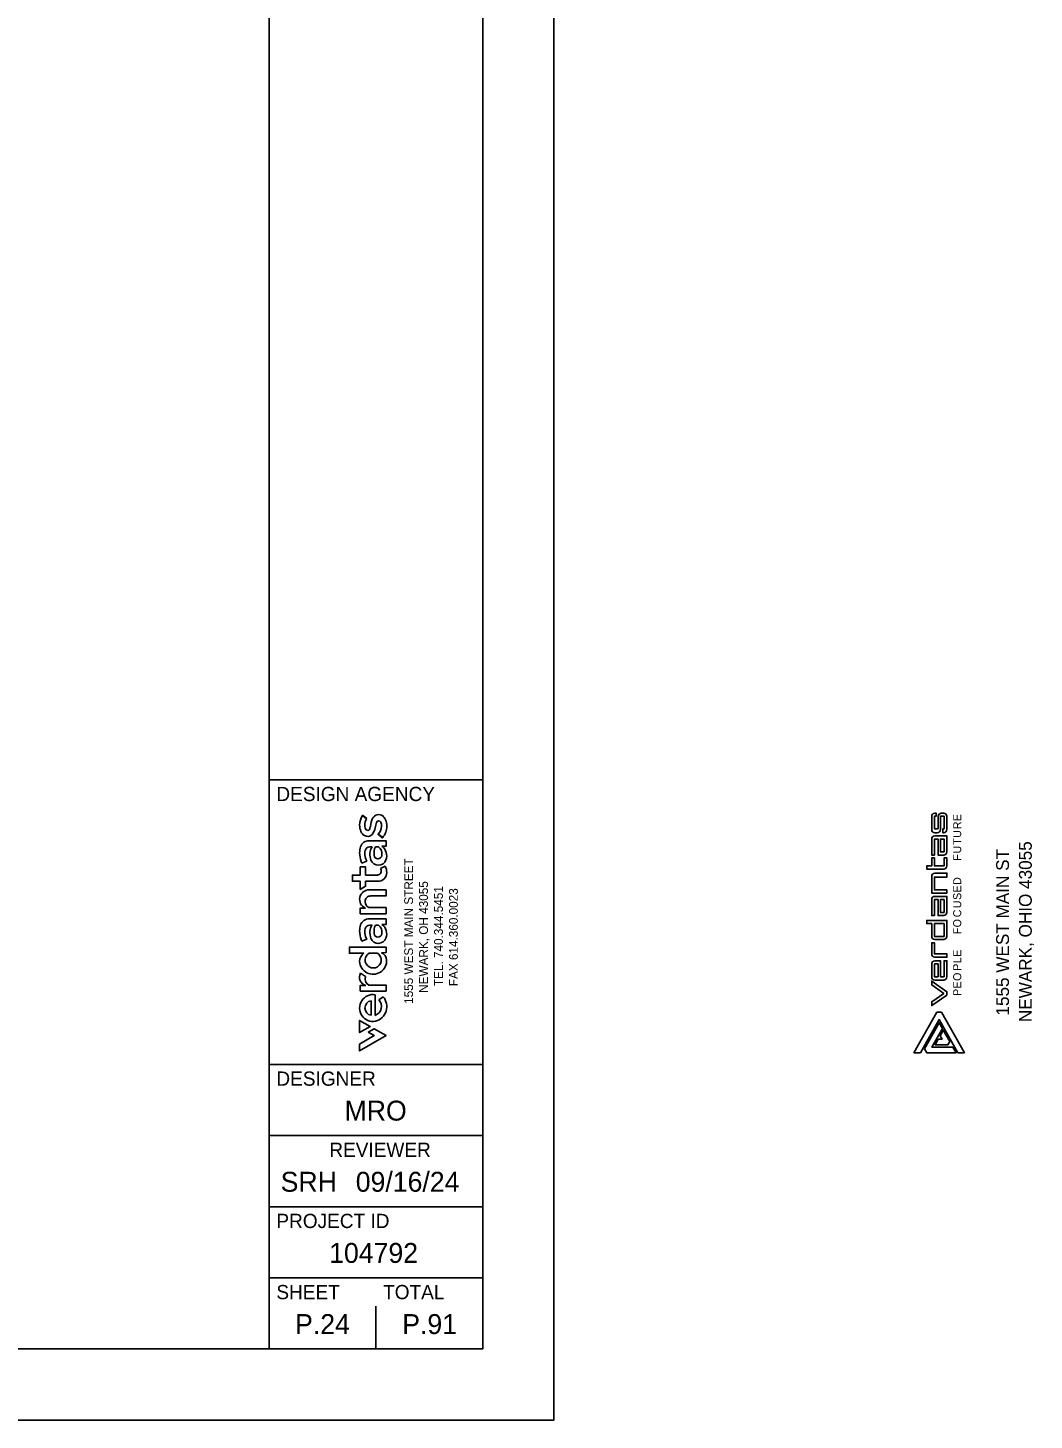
# Model space of a CAD drawing. Extents: x 0 to 37.4, y 0 to 22.
# Drawn here: x 30.3 to 37.37, y 0 to 9.78 of the extents above; entities that cross this region are included whole.
import ezdxf

# ---------------------------------------------------------------- set-up
doc = ezdxf.new("R2010")
doc.units = 0
for name, color, linetype in [('CS-ANNO-TTLB-LOGO', 7, 'Continuous'), ('Default', 7, 'Continuous'), ('SH_Border', 7, 'Continuous'), ('SH_Cut_Line', 7, 'Continuous'), ('SH_Data', 7, 'Continuous'), ('SH_Text', 7, 'Continuous')]:
    doc.layers.add(name, color=color, linetype=linetype)

msp = doc.modelspace()

# ---------------------------------------------------------------- linework, layer by layer
at = {"layer": 'CS-ANNO-TTLB-LOGO'}
for p, q in [((36.6549, 4.2432), (36.6549, 4.1504)), ((36.6858, 4.2657), (36.6774, 4.2657)), ((36.7392, 4.2657), (36.7224, 4.2657)), ((36.7617, 4.1504), (36.7617, 4.2432)), ((36.6774, 4.1279), (36.6942, 4.1279)), ((36.6549, 3.9704), (36.6549, 4.0829)), ((36.6549, 3.5456), (36.6549, 3.6581)), ((36.6774, 3.3769), (36.7392, 3.3769)), ((36.6549, 3.2053), (36.6549, 3.1153)), ((36.7617, 3.1153), (36.7617, 3.2278)), ((36.6774, 3.0928), (36.7392, 3.0928))]:
    msp.add_line(p, q, dxfattribs=at)
for points in [[(36.6999, 4.2432), (36.6999, 4.156), (36.6745, 4.156), (36.6745, 4.2432), (36.6858, 4.2432), (36.6858, 4.2657)], [(36.7167, 4.1504), (36.7167, 4.2432), (36.742, 4.2432), (36.742, 4.156), (36.7336, 4.156), (36.7336, 4.1279), (36.7392, 4.1279)], [(36.7392, 3.9704), (36.6999, 3.9704), (36.6999, 4.0829), (36.6745, 4.0829), (36.6745, 3.9704), (36.6549, 3.9704)], [(36.6774, 4.1054), (36.7617, 4.1054), (36.7617, 3.9929)], [(36.6202, 3.8944), (36.6549, 3.8944), (36.6549, 3.9506), (36.6745, 3.9506), (36.6745, 3.8944), (36.742, 3.8944), (36.742, 3.9506), (36.7617, 3.9506), (36.7617, 3.8944)], [(36.7392, 3.8719), (36.6202, 3.8719), (36.6202, 3.8944)], [(36.6549, 3.8213), (36.6549, 3.7031), (36.7617, 3.7031), (36.7617, 3.7256), (36.6745, 3.7256), (36.6745, 3.8156), (36.7617, 3.8156)], [(36.7617, 3.8156), (36.7617, 3.8438), (36.6774, 3.8438)], [(36.7392, 3.5456), (36.6999, 3.5456), (36.6999, 3.6581), (36.6745, 3.6581), (36.6745, 3.5456), (36.6549, 3.5456)], [(36.6774, 3.6806), (36.7617, 3.6806), (36.7617, 3.5681)], [(36.6202, 3.5119), (36.6202, 3.4894), (36.6549, 3.4894), (36.6549, 3.3994)], [(36.7617, 3.3994), (36.7617, 3.5119), (36.6202, 3.5119)], [(36.7617, 3.2756), (36.6745, 3.2756), (36.6745, 3.3544), (36.6549, 3.3544), (36.6549, 3.2756)], [(36.6774, 3.2531), (36.7617, 3.2531), (36.7617, 3.2756)], [(36.7617, 3.2278), (36.742, 3.2278), (36.742, 3.1153), (36.7167, 3.1153), (36.7167, 3.2278), (36.6774, 3.2278)]]:
    msp.add_lwpolyline(points, dxfattribs=at)
for points in [[(36.7167, 4.0829), (36.742, 4.0829), (36.742, 3.9929), (36.7167, 3.9929)], [(36.7167, 3.6581), (36.742, 3.6581), (36.742, 3.5681), (36.7167, 3.5681)], [(36.6745, 3.4894), (36.6745, 3.3994), (36.742, 3.3994), (36.742, 3.4894)], [(36.6999, 3.2053), (36.6745, 3.2053), (36.6745, 3.1153), (36.6999, 3.1153)], [(36.7393, 2.9991), (36.6549, 2.9399), (36.6549, 2.9125), (36.7617, 2.9873), (36.7622, 3.0105), (36.6553, 3.0853), (36.6549, 3.0582)]]:
    msp.add_lwpolyline(points, close=True, dxfattribs=at)
for centre, start, end in [((36.6774, 4.2432), 90, 180), ((36.7224, 4.2432), 90, 180), ((36.7392, 4.2432), 360, 90), ((36.6774, 4.1504), 180, 270), ((36.6942, 4.1504), 270, 0), ((36.7392, 4.1504), 270, 0), ((36.6774, 4.0829), 90, 180), ((36.7392, 3.9929), 270, 360), ((36.6774, 3.8213), 90, 180), ((36.7392, 3.8944), 270, 360), ((36.6774, 3.6581), 90, 180), ((36.7392, 3.5681), 270, 360), ((36.6774, 3.3994), 180, 270), ((36.7392, 3.3994), 270, 0), ((36.6774, 3.2756), 180, 270), ((36.6774, 3.2053), 90, 180), ((36.6774, 3.1153), 180, 270), ((36.7392, 3.1153), 270, 0)]:
    msp.add_arc(centre, 0.0225, start, end, dxfattribs=at)
at = {"layer": 'Default'}
for p, q in [((36.6549, 4.2432), (36.6549, 4.1504)), ((36.7392, 4.2657), (36.7224, 4.2657)), ((36.7617, 4.1504), (36.7617, 4.2432)), ((36.6774, 4.1279), (36.6942, 4.1279)), ((36.6774, 3.3769), (36.7392, 3.3769)), ((36.6549, 3.2053), (36.6549, 3.1153)), ((36.6774, 3.0928), (36.7392, 3.0928)), ((36.6043, 2.6089), (36.7077, 2.7921)), ((36.7303, 2.752), (36.6561, 2.6206)), ((36.7077, 2.7921), (36.7303, 2.752)), ((36.62, 2.5812), (36.6043, 2.6089)), ((36.8266, 2.5812), (36.62, 2.5812)), ((36.6561, 2.6206), (36.8044, 2.6206)), ((36.8044, 2.6206), (36.8266, 2.5812))]:
    msp.add_line(p, q, dxfattribs=at)
for points in [[(36.6999, 4.2432), (36.6999, 4.156), (36.6745, 4.156), (36.6745, 4.2432), (36.6858, 4.2432), (36.6858, 4.2657), (36.6774, 4.2657)], [(36.7167, 4.1504), (36.7167, 4.2432), (36.742, 4.2432), (36.742, 4.156), (36.7336, 4.156), (36.7336, 4.1279), (36.7392, 4.1279)], [(36.6549, 4.0829), (36.6549, 3.9704), (36.6745, 3.9704), (36.6745, 4.0829), (36.6999, 4.0829), (36.6999, 3.9704), (36.7392, 3.9704)], [(36.7617, 3.9929), (36.7617, 4.1054), (36.6774, 4.1054)], [(36.7617, 3.8944), (36.7617, 3.9506), (36.742, 3.9506), (36.742, 3.8944), (36.6745, 3.8944), (36.6745, 3.9506), (36.6549, 3.9506), (36.6549, 3.8944), (36.6202, 3.8944), (36.6202, 3.8719), (36.7392, 3.8719)], [(36.6549, 3.8213), (36.6549, 3.7031), (36.7617, 3.7031), (36.7617, 3.7256), (36.6745, 3.7256), (36.6745, 3.8156), (36.7617, 3.8156), (36.7617, 3.8438), (36.6774, 3.8438)], [(36.6549, 3.6581), (36.6549, 3.5456), (36.6745, 3.5456), (36.6745, 3.6581), (36.6999, 3.6581), (36.6999, 3.5456), (36.7392, 3.5456)], [(36.7617, 3.5681), (36.7617, 3.6806), (36.6774, 3.6806)], [(36.7617, 3.3994), (36.7617, 3.5119), (36.6202, 3.5119), (36.6202, 3.4894), (36.6549, 3.4894), (36.6549, 3.3994)], [(36.6774, 3.2531), (36.7617, 3.2531), (36.7617, 3.2756), (36.6745, 3.2756), (36.6745, 3.3544), (36.6549, 3.3544), (36.6549, 3.2756)], [(36.7617, 3.1153), (36.7617, 3.2278), (36.742, 3.2278), (36.742, 3.1153), (36.7167, 3.1153), (36.7167, 3.2278), (36.6774, 3.2278)]]:
    msp.add_lwpolyline(points, dxfattribs=at)
for points in [[(36.742, 4.0829), (36.742, 3.9929), (36.7167, 3.9929), (36.7167, 4.0829)], [(36.742, 3.6581), (36.742, 3.5681), (36.7167, 3.5681), (36.7167, 3.6581)], [(36.6745, 3.4894), (36.742, 3.4894), (36.742, 3.3994), (36.6745, 3.3994)], [(36.6999, 3.2053), (36.6999, 3.1153), (36.6745, 3.1153), (36.6745, 3.2053)], [(36.6549, 2.9399), (36.6549, 2.9125), (36.7617, 2.9873), (36.7622, 3.0105), (36.6553, 3.0853), (36.6549, 3.0582), (36.7393, 2.9991)], [(36.7077, 2.815), (36.8396, 2.5812), (36.8848, 2.5812), (36.7238, 2.8665), (36.6915, 2.8665), (36.5306, 2.5812), (36.5758, 2.5812)], [(36.5758, 2.5812), (36.7077, 2.815), (36.8396, 2.5812), (36.8848, 2.5812), (36.7238, 2.8665), (36.6915, 2.8665), (36.5306, 2.5812)], [(36.6043, 2.6089), (36.62, 2.5812), (36.8266, 2.5812), (36.8044, 2.6206), (36.6561, 2.6206), (36.7303, 2.752), (36.7077, 2.7921)], [(36.7008, 2.6768), (36.6786, 2.6374), (36.769, 2.6374), (36.7819, 2.6604), (36.7367, 2.7406), (36.7141, 2.7005), (36.7275, 2.6768)], [(36.7008, 2.6768), (36.7275, 2.6768), (36.7141, 2.7005), (36.7367, 2.7406), (36.7819, 2.6604), (36.769, 2.6374), (36.6786, 2.6374)]]:
    msp.add_lwpolyline(points, close=True, dxfattribs=at)
for centre, start, end in [((36.6774, 4.2432), 90, 180), ((36.7224, 4.2432), 90, 180), ((36.7392, 4.2432), 360, 90), ((36.6774, 4.1504), 180, 270), ((36.6942, 4.1504), 270, 0), ((36.7392, 4.1504), 270, 0), ((36.6774, 4.0829), 90, 180), ((36.7392, 3.9929), 270, 0), ((36.6774, 3.8213), 90, 180), ((36.7392, 3.8944), 270, 0), ((36.6774, 3.6581), 90, 180), ((36.7392, 3.5681), 270, 0), ((36.6774, 3.3994), 180, 270), ((36.7392, 3.3994), 270, 0), ((36.6774, 3.2756), 180, 270), ((36.6774, 3.2053), 90, 180), ((36.6774, 3.1153), 180, 270), ((36.7392, 3.1153), 270, 0)]:
    msp.add_arc(centre, 0.0225, start, end, dxfattribs=at)
at = {"layer": 'SH_Border'}
for p, q in [((32, 0.5), (32, 21.5)), ((32, 4.5), (33.5, 4.5)), ((32, 2.5), (33.5, 2.5)), ((32, 2), (33.5, 2)), ((32, 1.5), (33.5, 1.5)), ((32, 1), (33.5, 1))]:
    msp.add_line(p, q, dxfattribs=at)
msp.add_lwpolyline([(1.5, 21.5), (33.5, 21.5), (33.5, 0.5), (1.5, 0.5)], close=True, dxfattribs=at)
at = {"layer": 'SH_Cut_Line'}
msp.add_lwpolyline([(0, 0), (34, 0), (34, 22), (0, 22)], close=True, dxfattribs=at)
at = {"layer": 'SH_Data'}
for p, q in [((32.75, 3.5), (32.75, 3.5)), ((32.75, 0.5), (32.75, 0.8)), ((32.375, 0.675), (32.375, 0.675))]:
    msp.add_line(p, q, dxfattribs=at)
at = {"layer": 'SH_Text'}
for p, q in [((32.6845, 4.2263), (32.655, 4.2488)), ((32.7172, 4.2018), (32.7108, 4.1722)), ((32.745, 4.1621), (32.749, 4.181)), ((32.7664, 4.1165), (32.7975, 4.0939)), ((32.7069, 4.0286), (32.7221, 4.0286)), ((32.7463, 4.0286), (32.7683, 4.0286)), ((32.6463, 3.9261), (32.6509, 3.9147)), ((32.8149, 3.8922), (32.7815, 3.8767)), ((32.7069, 3.4791), (32.7221, 3.4791)), ((32.7463, 3.4791), (32.7683, 3.4791)), ((32.6463, 3.3765), (32.6509, 3.3651)), ((32.7017, 3.2812), (32.759, 3.2812)), ((32.6758, 3.1185), (32.6407, 3.1397)), ((32.7158, 2.947), (32.7158, 2.8451)), ((32.7445, 2.8443), (32.7445, 2.9896)), ((32.801, 2.9757), (32.7703, 2.9546))]:
    msp.add_line(p, q, dxfattribs=at)
for points in [[(32.6861, 4.2287), (32.6559, 4.25), (32.655, 4.2488)], [(32.6845, 4.2263), (32.6861, 4.2287)], [(32.7172, 4.2018), (32.7108, 4.1722)], [(32.745, 4.1621), (32.749, 4.181)], [(32.7664, 4.1165), (32.7642, 4.1142), (32.7942, 4.0904), (32.7975, 4.0939)], [(32.7922, 4.0323), (32.8208, 4.0323), (32.8208, 4.0718), (32.702, 4.0718)], [(32.7922, 4.0323), (32.8208, 4.0323), (32.8208, 4.0718), (32.702, 4.0718)], [(32.7069, 4.0286), (32.7221, 4.0286)], [(32.7683, 4.0286), (32.7463, 4.0286)], [(32.6463, 3.9261), (32.6509, 3.9147)], [(32.6509, 3.9147), (32.6847, 3.9285), (32.6812, 3.9374)], [(32.6509, 3.9147), (32.6847, 3.9285), (32.6812, 3.9374)], [(32.7546, 3.8297), (32.6769, 3.8297), (32.6769, 3.8877), (32.6399, 3.8877), (32.6399, 3.8297), (32.5844, 3.8297), (32.5844, 3.7865), (32.6399, 3.7865), (32.6399, 3.7299), (32.6769, 3.7521), (32.6769, 3.7865), (32.7622, 3.7865)], [(32.7546, 3.8297), (32.6769, 3.8297), (32.6769, 3.8877), (32.6399, 3.8877), (32.6399, 3.8297), (32.5844, 3.8297), (32.5844, 3.7865), (32.6399, 3.7865), (32.6399, 3.7299), (32.6769, 3.7521), (32.6769, 3.7865), (32.7622, 3.7865)], [(32.8149, 3.8922), (32.7815, 3.8767)], [(32.7147, 3.6831), (32.8208, 3.6831), (32.8208, 3.7263), (32.7027, 3.7263)], [(32.7147, 3.6831), (32.8208, 3.6831), (32.8208, 3.7263), (32.7027, 3.7263)], [(32.6753, 3.5982), (32.6399, 3.5982), (32.6399, 3.5582), (32.8208, 3.5582), (32.8208, 3.6014), (32.6998, 3.6014)], [(32.6753, 3.5982), (32.6399, 3.5982), (32.6399, 3.5582), (32.8208, 3.5582), (32.8208, 3.6014), (32.6998, 3.6014)], [(32.7922, 3.4827), (32.8208, 3.4827), (32.8208, 3.5223), (32.702, 3.5223)], [(32.7922, 3.4827), (32.8208, 3.4827), (32.8208, 3.5223), (32.702, 3.5223)], [(32.7069, 3.4791), (32.7221, 3.4791)], [(32.7683, 3.4791), (32.7463, 3.4791)], [(32.6463, 3.3765), (32.6509, 3.3651)], [(32.6509, 3.3651), (32.6847, 3.3789), (32.6812, 3.3878)], [(32.6509, 3.3651), (32.6847, 3.3789), (32.6812, 3.3878)], [(32.6648, 3.2812), (32.5631, 3.2812), (32.5631, 3.3244), (32.8208, 3.3244), (32.8208, 3.2849), (32.789, 3.2848)], [(32.789, 3.2848), (32.8208, 3.2849), (32.8208, 3.3244), (32.5631, 3.3244), (32.5631, 3.2812), (32.6648, 3.2812)], [(32.7017, 3.2812), (32.759, 3.2812)], [(32.6758, 3.1185), (32.6407, 3.1397)], [(32.6786, 3.0546), (32.6398, 3.0546), (32.6398, 3.0152), (32.8207, 3.0152), (32.8207, 3.0569), (32.7008, 3.0569)], [(32.6786, 3.0546), (32.6398, 3.0546), (32.6398, 3.0152), (32.8207, 3.0152), (32.8207, 3.0569), (32.7008, 3.0569)], [(32.7158, 2.8451), (32.7158, 2.947)], [(32.7445, 2.8443), (32.7445, 2.9896)], [(32.801, 2.9757), (32.7703, 2.9546)], [(32.6351, 2.8093), (32.6351, 2.723), (32.7098, 2.7661), (32.6351, 2.8093)], [(32.6958, 2.7267), (32.7381, 2.7022), (32.6351, 2.6427), (32.6351, 2.5951), (32.8205, 2.7022), (32.737, 2.7504), (32.6958, 2.7267)]]:
    msp.add_lwpolyline(points, dxfattribs=at)
for points in [[(32.7098, 2.7661), (32.6351, 2.723), (32.6351, 2.8093)], [(32.6958, 2.7267), (32.7381, 2.7022), (32.6351, 2.6427), (32.6351, 2.5951), (32.8205, 2.7022), (32.737, 2.7504)]]:
    msp.add_lwpolyline(points, close=True, dxfattribs=at)
for centre, radius, start, end in [((32.7599, 4.1812), 0.1247, 147.22328, 179.84204), ((32.7599, 4.1812), 0.1247, 147.22328, 179.84204), ((32.761, 4.1787), 0.0901, 148.12326, 178.11353), ((32.761, 4.1787), 0.0901, 148.12326, 178.11353), ((32.8373, 4.1746), 0.1232, 154.04469, 167.21491), ((32.8373, 4.1746), 0.1232, 154.04469, 167.21491), ((32.7687, 4.2081), 0.0468, 52.70919, 154.21664), ((32.7687, 4.2081), 0.0468, 52.70919, 154.21664), ((32.7694, 4.1954), 0.0157, 26.91646, 163.60196), ((32.7694, 4.1954), 0.0157, 26.91646, 163.60196), ((32.7543, 4.1931), 0.0675, 22.82777, 50.71565), ((32.7543, 4.1931), 0.0675, 22.82777, 50.71565), ((32.7119, 4.175), 0.1136, 359.0192, 22.9257), ((32.7119, 4.175), 0.1136, 359.0192, 22.9257), ((32.7433, 4.1797), 0.1082, 179.01095, 203.55998), ((32.7433, 4.1797), 0.1082, 179.01095, 203.55998), ((32.7026, 4.1617), 0.0637, 203.36923, 237.807), ((32.7026, 4.1617), 0.0637, 203.36923, 237.807), ((32.6911, 4.1451), 0.0435, 238.94525, 317.68291), ((32.6911, 4.1451), 0.0435, 238.94525, 317.68291), ((32.7377, 4.1806), 0.0667, 179.05393, 195.69208), ((32.7377, 4.1806), 0.0667, 179.05393, 195.69208), ((32.7044, 4.1702), 0.0318, 193.85614, 223.71908), ((32.7044, 4.1702), 0.0318, 193.85614, 223.71908), ((32.6914, 4.1581), 0.0141, 224.78223, 330.43657), ((32.6914, 4.1581), 0.0141, 224.78223, 330.43657), ((32.6343, 4.1866), 0.0778, 332.90022, 349.38313), ((32.6343, 4.1866), 0.0778, 332.90022, 349.38313), ((32.6466, 4.1799), 0.1, 320.12588, 349.70225), ((32.6466, 4.1799), 0.1, 320.12588, 349.70225), ((32.838, 4.1664), 0.0902, 158.18628, 170.63281), ((32.838, 4.1664), 0.0902, 158.18628, 170.63281), ((32.7013, 4.1765), 0.0885, 317.36304, 356.92436), ((32.7013, 4.1765), 0.0885, 317.36304, 356.92436), ((32.7276, 4.175), 0.0622, 357.00773, 26.31116), ((32.7276, 4.175), 0.0622, 357.00773, 26.31116), ((32.7025, 4.1721), 0.123, 320.51657, 0.43409), ((32.7025, 4.1721), 0.123, 320.51657, 0.43409), ((32.757, 3.989), 0.1218, 160.81276, 180.93166), ((32.757, 3.989), 0.1218, 160.81276, 180.93166), ((32.7, 4.0111), 0.0607, 88.07599, 162.86424), ((32.7, 4.0111), 0.0607, 88.07599, 162.86424), ((32.7087, 3.9932), 0.0355, 92.96709, 165.223), ((32.7087, 3.9932), 0.0355, 92.96709, 165.223), ((32.8099, 3.9746), 0.1031, 148.34975, 202.47075), ((32.8099, 3.9746), 0.1031, 148.34975, 202.47075), ((32.8357, 3.9847), 0.0996, 153.83718, 188.87457), ((32.8357, 3.9847), 0.0996, 153.83718, 188.87457), ((32.7313, 3.9807), 0.0605, 348.12474, 52.36783), ((32.7313, 3.9807), 0.0605, 348.12474, 52.36783), ((32.7441, 3.9666), 0.0814, 338.27739, 53.79489), ((32.7441, 3.9666), 0.0814, 338.27739, 53.79489), ((32.8238, 3.9901), 0.1886, 180.9467, 199.83537), ((32.8238, 3.9901), 0.1886, 180.9467, 199.83537), ((32.7333, 3.9845), 0.0615, 163.25224, 179.99706), ((32.7333, 3.9845), 0.0615, 163.25224, 179.99706), ((32.8157, 3.9887), 0.144, 181.66161, 200.87137), ((32.8157, 3.9887), 0.144, 181.66161, 200.87137), ((32.7669, 3.956), 0.0563, 201.67635, 339.72677), ((32.7669, 3.956), 0.0563, 201.67635, 339.72677), ((32.7639, 3.9704), 0.0267, 182.32704, 355.37776), ((32.7639, 3.9704), 0.0267, 182.32704, 355.37776), ((32.7572, 3.8595), 0.0298, 265.06923, 356.35481), ((32.7572, 3.8595), 0.0298, 265.06923, 356.35481), ((32.7645, 3.8475), 0.061, 267.86409, 1.62134), ((32.7645, 3.8475), 0.061, 267.86409, 1.62134), ((32.746, 3.8562), 0.041, 1.86376, 29.96515), ((32.746, 3.8562), 0.041, 1.86376, 29.96515), ((32.7364, 3.85), 0.0892, 359.5424, 28.24947), ((32.7364, 3.85), 0.0892, 359.5424, 28.24947), ((32.7015, 3.6596), 0.0668, 88.98961, 246.91113), ((32.7015, 3.6596), 0.0668, 88.98961, 246.91113), ((32.7149, 3.6443), 0.0412, 137.30492, 182.96879), ((32.7149, 3.6443), 0.0412, 137.30492, 182.96879), ((32.7191, 3.6425), 0.0453, 180.34657, 244.91134), ((32.7191, 3.6425), 0.0453, 180.34657, 244.91134), ((32.7125, 3.6421), 0.0411, 86.97388, 132.7421), ((32.7125, 3.6421), 0.0411, 86.97388, 132.7421), ((32.7, 3.4616), 0.0607, 88.07599, 162.86424), ((32.7, 3.4616), 0.0607, 88.07599, 162.86424), ((32.757, 3.4394), 0.1218, 160.81276, 180.93166), ((32.757, 3.4394), 0.1218, 160.81276, 180.93166), ((32.8238, 3.4405), 0.1886, 180.9467, 199.83537), ((32.8238, 3.4405), 0.1886, 180.9467, 199.83537), ((32.7333, 3.4349), 0.0615, 163.25224, 179.99706), ((32.7333, 3.4349), 0.0615, 163.25224, 179.99706), ((32.8157, 3.4391), 0.144, 181.66161, 200.87137), ((32.8157, 3.4391), 0.144, 181.66161, 200.87137), ((32.7087, 3.4436), 0.0355, 92.96709, 165.223), ((32.7087, 3.4436), 0.0355, 92.96709, 165.223), ((32.8099, 3.425), 0.1031, 148.34975, 202.47075), ((32.8099, 3.425), 0.1031, 148.34975, 202.47075), ((32.8357, 3.4352), 0.0996, 153.83718, 188.87457), ((32.8357, 3.4352), 0.0996, 153.83718, 188.87457), ((32.7313, 3.4312), 0.0605, 348.12474, 52.36783), ((32.7313, 3.4312), 0.0605, 348.12474, 52.36783), ((32.7441, 3.417), 0.0814, 338.27739, 53.79489), ((32.7441, 3.417), 0.0814, 338.27739, 53.79489), ((32.7669, 3.4064), 0.0563, 201.67635, 339.72677), ((32.7669, 3.4064), 0.0563, 201.67635, 339.72677), ((32.7639, 3.4209), 0.0267, 182.32704, 355.37776), ((32.7639, 3.4209), 0.0267, 182.32704, 355.37776), ((32.703, 3.2252), 0.0678, 124.28433, 181.27226), ((32.703, 3.2252), 0.0678, 124.28433, 181.27226), ((32.7301, 3.2282), 0.095, 182.77189, 2.9779), ((32.7301, 3.2282), 0.095, 182.77189, 2.9779), ((32.7303, 3.2337), 0.0565, 176.4529, 5.05495), ((32.7303, 3.2337), 0.0565, 176.4529, 5.05495), ((32.7294, 3.2329), 0.0557, 119.90067, 175.57974), ((32.7294, 3.2329), 0.0557, 119.90067, 175.57974), ((32.7311, 3.2328), 0.0559, 6.06662, 60.04101), ((32.7311, 3.2328), 0.0559, 6.06662, 60.04101), ((32.7615, 3.2273), 0.0638, 5.30838, 64.52521), ((32.7615, 3.2273), 0.0638, 5.30838, 64.52521), ((32.6937, 3.1123), 0.0597, 152.6524, 255.29294), ((32.6937, 3.1123), 0.0597, 152.6524, 255.29294), ((32.7251, 3.1027), 0.0518, 162.13838, 242.04081), ((32.7251, 3.1027), 0.0518, 162.13838, 242.04081), ((32.7298, 2.8962), 0.0946, 81.04458, 280.25771), ((32.7298, 2.8962), 0.0946, 81.04458, 280.25771), ((32.7237, 2.896), 0.0516, 98.83779, 261.16221), ((32.7237, 2.896), 0.0516, 98.83779, 261.16221), ((32.7201, 2.9082), 0.0684, 290.92317, 42.73906), ((32.7201, 2.9082), 0.0684, 290.92317, 42.73906), ((32.7175, 2.9071), 0.1081, 285.66678, 39.36993), ((32.7175, 2.9071), 0.1081, 285.66678, 39.36993)]:
    msp.add_arc(centre, radius, start, end, dxfattribs=at)

# ---------------------------------------------------------------- texts
at = {"layer": 'Default'}
for s, p in [('E', (36.8625, 4.2083)), ('R', (36.8625, 4.1525)), ('U', (36.8625, 4.0916)), ('T', (36.8625, 4.043)), ('U', (36.8625, 3.9822)), ('F', (36.8625, 3.9309)), ('D', (36.8625, 3.7607)), ('E', (36.8625, 3.7079)), ('S', (36.8625, 3.6553)), ('U', (36.8625, 3.5968)), ('C', (36.8625, 3.5337)), ('O', (36.8625, 3.4626)), ('F', (36.8625, 3.4137)), ('E', (36.8625, 3.2556)), ('L', (36.8625, 3.2103)), ('O', (36.8625, 3.0863)), ('P', (36.8625, 3.1576)), ('E', (36.8625, 3.0333)), ('P', (36.8625, 2.9805))]:
    msp.add_text(s, height=0.0563, rotation=90, dxfattribs=at).set_placement(p)
at = {"layer": 'SH_Data'}
for s, height, p in [('DESIGN AGENCY', 0.1, (32.05, 4.35)), ('DESIGNER', 0.1, (32.05, 2.35)), ('MRO', 0.14, (32.5292, 2.105)), ('REVIEWER', 0.1, (32.4218, 1.85)), ('SRH', 0.14, (32.08, 1.605)), ('09/16/24', 0.14, (32.6078, 1.605)), ('PROJECT ID', 0.1, (32.05, 1.35)), ('104792', 0.14, (32.4209, 1.105)), ('SHEET', 0.1, (32.05, 0.85)), ('TOTAL', 0.1, (32.8, 0.85)), ('P.24', 0.14, (32.1816, 0.605)), ('P.91', 0.14, (32.9344, 0.605))]:
    msp.add_text(s, height=height, dxfattribs=at).set_placement(p)
at = {"layer": 'SH_Text'}
for s, height, p in [('NEWARK, OHIO 43055', 0.09, (37.3582, 2.7968)), ('1555 WEST MAIN STREET', 0.06172, (33.0102, 2.925)), ('1555 WEST MAIN ST', 0.09, (37.1982, 2.843)), ('NEWARK, OH 43055', 0.06172, (33.1151, 3.0028)), ('TEL. 740.344.5451', 0.06172, (33.22, 3.05)), ('FAX 614.360.0023', 0.06172, (33.3251, 3.0494))]:
    msp.add_text(s, height=height, rotation=90, dxfattribs=at).set_placement(p)

doc.saveas('drawing.dxf')
